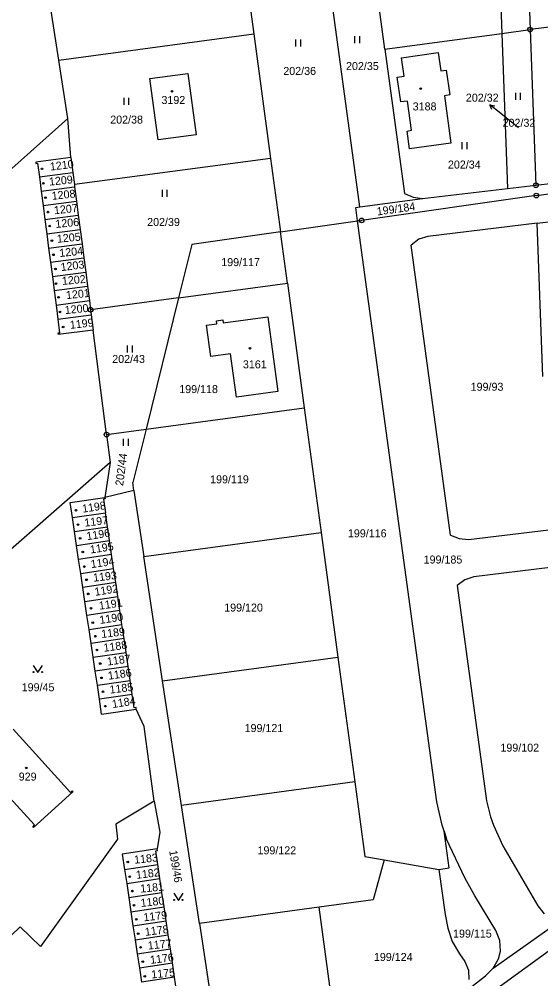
# Model space of a CAD drawing. Extents: x -735249 to -729401, y -1124843 to -1121828.
# Drawn here: x -732943.4 to -732832.6, y -1123775.2 to -1123571.3 of the extents above; entities that cross this region are included whole.
import ezdxf

# ---------------------------------------------------------------- set-up
doc = ezdxf.new("R2010")
doc.units = 0
for name, color, linetype in [('Vrstva 1', 7, 'Continuous'), ('Vrstva 16', 7, 'Continuous'), ('Vrstva 18', 7, 'Continuous'), ('Vrstva 19', 7, 'Continuous'), ('Vrstva 25', 7, 'Continuous')]:
    doc.layers.add(name, color=color, linetype=linetype)

msp = doc.modelspace()

# ---------------------------------------------------------------- linework, layer by layer
at = {"layer": 'Vrstva 1'}
for points in [[(-732842, -1123542.92), (-732840.85, -1123574.33)], [(-732836.01, -1123542.25), (-732834.87, -1123573.52)], [(-732871.03, -1123611.19), (-732879.7, -1123546.83)], [(-732865.69, -1123577.69), (-732869.97, -1123546.01)], [(-732897.13, -1123547.94), (-732893.56, -1123574.4)], [(-732934.95, -1123580.03), (-732936.92, -1123567.25)], [(-732817.38, -1123571.4), (-732834.87, -1123573.52)], [(-732840.85, -1123574.33), (-732834.87, -1123573.52)], [(-732834.87, -1123573.52), (-732833.63, -1123606.6)], [(-732934.95, -1123580.03), (-732893.56, -1123574.4)], [(-732893.56, -1123574.4), (-732889.98, -1123600.89)], [(-732865.69, -1123577.69), (-732840.85, -1123574.33)], [(-732840.85, -1123574.33), (-732839.65, -1123607.29)], [(-732865.69, -1123577.69), (-732861.55, -1123608.36)], [(-732862.15, -1123579.48), (-732854.39, -1123578.35)], [(-732861.61, -1123583.4), (-732862.15, -1123579.48)], [(-732854.39, -1123578.35), (-732853.79, -1123582.31)], [(-732933.04, -1123592.37), (-732934.95, -1123580.03)], [(-732915.61, -1123583.93), (-732907.52, -1123582.85)], [(-732907.52, -1123582.85), (-732905.79, -1123595.87)], [(-732863.07, -1123583.62), (-732861.61, -1123583.4)], [(-732862.32, -1123588.88), (-732863.07, -1123583.62)], [(-732853.79, -1123582.31), (-732852.65, -1123582.15)], [(-732852.65, -1123582.15), (-732851.87, -1123587.41)], [(-732913.86, -1123596.95), (-732915.61, -1123583.93)], [(-732851.87, -1123587.41), (-732853.07, -1123587.62)], [(-732853.07, -1123587.62), (-732851.7, -1123597.62)], [(-732860.86, -1123588.74), (-732862.32, -1123588.88)], [(-732860.02, -1123594.89), (-732860.86, -1123588.74)], [(-732933.04, -1123592.37), (-732988.63, -1123641.96)], [(-732932.39, -1123600.7), (-732933.04, -1123592.37)], [(-732905.79, -1123595.87), (-732913.86, -1123596.95)], [(-732860.98, -1123595.07), (-732860.02, -1123594.89)], [(-732860.49, -1123598.84), (-732860.98, -1123595.07)], [(-732851.7, -1123597.62), (-732860.49, -1123598.84)], [(-732932.39, -1123600.7), (-732939.85, -1123601.67)], [(-732939.85, -1123601.67), (-732939.82, -1123601.94)], [(-732939.82, -1123601.94), (-732939.45, -1123601.89)], [(-732939.45, -1123601.89), (-732939.07, -1123604.81)], [(-732932.39, -1123600.7), (-732931.98, -1123603.89)], [(-732889.98, -1123600.89), (-732931.64, -1123606.45)], [(-732889.98, -1123600.89), (-732887.87, -1123616.49)], [(-732939.07, -1123604.81), (-732931.98, -1123603.89)], [(-732931.98, -1123603.89), (-732931.64, -1123606.45)], [(-732939.07, -1123604.81), (-732938.68, -1123607.83)], [(-732938.68, -1123607.83), (-732931.58, -1123606.91)], [(-732938.68, -1123607.83), (-732938.28, -1123610.87)], [(-732931.64, -1123606.45), (-732931.58, -1123606.91)], [(-732931.58, -1123606.91), (-732931.19, -1123609.94)], [(-732857.69, -1123609.38), (-732839.65, -1123607.29)], [(-732839.65, -1123607.29), (-732833.63, -1123606.6)], [(-732833.63, -1123606.6), (-732830, -1123606.18)], [(-732938.28, -1123610.87), (-732931.19, -1123609.94)], [(-732931.19, -1123609.94), (-732930.8, -1123612.95)], [(-732871.03, -1123611.19), (-732857.69, -1123609.38)], [(-732833.55, -1123608.79), (-732870.64, -1123614.05)], [(-732861.55, -1123608.36), (-732859.69, -1123609.13)], [(-732859.69, -1123609.13), (-732857.69, -1123609.38)], [(-732833.55, -1123608.79), (-732830.81, -1123608.4)], [(-732938.28, -1123610.87), (-732937.89, -1123613.88)], [(-732871.87, -1123611.3), (-732871.03, -1123611.19)], [(-732871.48, -1123614.17), (-732871.87, -1123611.3)], [(-732833.34, -1123614.64), (-732801.13, -1123610.73)], [(-732937.89, -1123613.88), (-732930.8, -1123612.95)], [(-732937.89, -1123613.88), (-732937.5, -1123616.9)], [(-732930.8, -1123612.95), (-732930.41, -1123615.98)], [(-732887.87, -1123616.49), (-732871.48, -1123614.17)], [(-732871.48, -1123614.17), (-732870.64, -1123614.05)], [(-732854.63, -1123737.58), (-732871.48, -1123614.17)], [(-732937.5, -1123616.9), (-732930.41, -1123615.98)], [(-732930.41, -1123615.98), (-732930.01, -1123619.01)], [(-732833.34, -1123614.64), (-732856.61, -1123617.46)], [(-732832.12, -1123647.23), (-732833.34, -1123614.64)], [(-732937.5, -1123616.9), (-732937.1, -1123619.93)], [(-732887.87, -1123616.49), (-732906.73, -1123619.17)], [(-732886.4, -1123627.38), (-732887.87, -1123616.49)], [(-732858.51, -1123618.07), (-732860.1, -1123619.29)], [(-732856.61, -1123617.46), (-732858.51, -1123618.07)], [(-732937.1, -1123619.93), (-732930.01, -1123619.01)], [(-732937.1, -1123619.93), (-732936.71, -1123622.94)], [(-732930.01, -1123619.01), (-732929.62, -1123622.02)], [(-732906.73, -1123619.17), (-732909.53, -1123630.51)], [(-732851.77, -1123680.94), (-732860.1, -1123619.29)], [(-732936.71, -1123622.94), (-732929.62, -1123622.02)], [(-732929.62, -1123622.02), (-732929.23, -1123625.04)], [(-732936.71, -1123622.94), (-732936.32, -1123625.96)], [(-732936.32, -1123625.96), (-732929.23, -1123625.04)], [(-732936.32, -1123625.96), (-732935.93, -1123628.98)], [(-732929.23, -1123625.04), (-732928.84, -1123628.06)], [(-732935.93, -1123628.98), (-732928.84, -1123628.06)], [(-732928.84, -1123628.06), (-732928.44, -1123631.11)], [(-732909.53, -1123630.51), (-732886.4, -1123627.38)], [(-732886.4, -1123627.38), (-732882.82, -1123653.88)], [(-732935.93, -1123628.98), (-732935.53, -1123632.04)], [(-732909.53, -1123630.51), (-732928.19, -1123633.03)], [(-732909.53, -1123630.51), (-732916.42, -1123658.42)], [(-732935.53, -1123632.04), (-732928.44, -1123631.11)], [(-732935.53, -1123632.04), (-732935.14, -1123635.05)], [(-732928.44, -1123631.11), (-732928.19, -1123633.03)], [(-732935.14, -1123635.05), (-732928.05, -1123634.12)], [(-732928.19, -1123633.03), (-732928.05, -1123634.12)], [(-732928.05, -1123634.12), (-732927.63, -1123637.35)], [(-732900.01, -1123635.84), (-732890.56, -1123634.57)], [(-732890.56, -1123634.57), (-732888.44, -1123650.41)], [(-732935.14, -1123635.05), (-732934.78, -1123638)], [(-732903.56, -1123636.32), (-732901.38, -1123636.03)], [(-732902.65, -1123643), (-732903.56, -1123636.32)], [(-732901.46, -1123635.38), (-732900.09, -1123635.2)], [(-732901.38, -1123636.03), (-732901.46, -1123635.38)], [(-732900.09, -1123635.2), (-732900.01, -1123635.84)], [(-732934.78, -1123638), (-732935.13, -1123638.04)], [(-732935.13, -1123638.04), (-732935.09, -1123638.32)], [(-732927.63, -1123637.35), (-732935.09, -1123638.32)], [(-732924.81, -1123659.55), (-732927.63, -1123637.35)], [(-732898.45, -1123642.43), (-732902.65, -1123643)], [(-732897.21, -1123651.59), (-732898.45, -1123642.43)], [(-732888.44, -1123650.41), (-732897.21, -1123651.59)], [(-732916.42, -1123658.42), (-732882.82, -1123653.88)], [(-732882.82, -1123653.88), (-732879.24, -1123680.38)], [(-732924.81, -1123659.55), (-732916.42, -1123658.42)], [(-732916.42, -1123658.42), (-732919.22, -1123669.78)], [(-732924.81, -1123659.55), (-732924.06, -1123665.47)], [(-732924.06, -1123665.47), (-732971.48, -1123706.97)], [(-732924.06, -1123665.47), (-732925.16, -1123672.93)], [(-732919.02, -1123671.48), (-732919.22, -1123669.78)], [(-732932.52, -1123674.02), (-732925.16, -1123672.93)], [(-732925.11, -1123673.24), (-732925.49, -1123673.29)], [(-732925.49, -1123673.29), (-732925.06, -1123676.16)], [(-732919.02, -1123671.48), (-732925.16, -1123672.93)], [(-732925.16, -1123672.93), (-732925.11, -1123673.24)], [(-732919.02, -1123671.48), (-732916.9, -1123685.46)], [(-732932.05, -1123677.2), (-732932.52, -1123674.02)], [(-732932.05, -1123677.2), (-732925.06, -1123676.16)], [(-732931.61, -1123680.17), (-732932.05, -1123677.2)], [(-732924.62, -1123679.13), (-732925.06, -1123676.16)], [(-732931.61, -1123680.17), (-732924.62, -1123679.13)], [(-732924.18, -1123682.1), (-732924.62, -1123679.13)], [(-732931.17, -1123683.14), (-732931.61, -1123680.17)], [(-732916.9, -1123685.46), (-732879.24, -1123680.38)], [(-732879.24, -1123680.38), (-732875.66, -1123706.88)], [(-732851.77, -1123680.94), (-732849.9, -1123681.64)], [(-732847.91, -1123681.88), (-732830.9, -1123679.81)], [(-732931.17, -1123683.14), (-732924.18, -1123682.1)], [(-732930.73, -1123686.11), (-732931.17, -1123683.14)], [(-732923.74, -1123685.07), (-732924.18, -1123682.1)], [(-732849.9, -1123681.64), (-732847.91, -1123681.88)], [(-732923.74, -1123685.07), (-732930.73, -1123686.11)], [(-732923.3, -1123688.04), (-732923.74, -1123685.07)], [(-732912.9, -1123711.92), (-732916.9, -1123685.46)], [(-732930.29, -1123689.08), (-732930.73, -1123686.11)], [(-732930.29, -1123689.08), (-732923.3, -1123688.04)], [(-732929.85, -1123692.05), (-732930.29, -1123689.08)], [(-732922.86, -1123691.01), (-732923.3, -1123688.04)], [(-732830.6, -1123687.83), (-732846.84, -1123689.8)], [(-732922.86, -1123691.01), (-732929.85, -1123692.05)], [(-732922.42, -1123693.98), (-732922.86, -1123691.01)], [(-732848.74, -1123690.41), (-732850.33, -1123691.63)], [(-732850.33, -1123691.63), (-732844.15, -1123737.41)], [(-732846.84, -1123689.8), (-732848.74, -1123690.41)], [(-732929.4, -1123695.02), (-732929.85, -1123692.05)], [(-732929.4, -1123695.02), (-732922.42, -1123693.98)], [(-732928.96, -1123697.98), (-732929.4, -1123695.02)], [(-732921.98, -1123696.95), (-732922.42, -1123693.98)], [(-732921.98, -1123696.95), (-732928.96, -1123697.98)], [(-732921.54, -1123699.92), (-732921.98, -1123696.95)], [(-732928.52, -1123700.95), (-732928.96, -1123697.98)], [(-732928.52, -1123700.95), (-732921.54, -1123699.92)], [(-732921.1, -1123702.89), (-732921.54, -1123699.92)], [(-732928.08, -1123703.92), (-732928.52, -1123700.95)], [(-732921.1, -1123702.89), (-732928.08, -1123703.92)], [(-732927.64, -1123706.88), (-732928.08, -1123703.92)], [(-732920.66, -1123705.85), (-732921.1, -1123702.89)], [(-732927.64, -1123706.88), (-732920.66, -1123705.85)], [(-732920.22, -1123708.82), (-732920.66, -1123705.85)], [(-732927.2, -1123709.85), (-732927.64, -1123706.88)], [(-732912.9, -1123711.92), (-732875.66, -1123706.88)], [(-732875.66, -1123706.88), (-732872.08, -1123733.38)], [(-732920.22, -1123708.82), (-732927.2, -1123709.85)], [(-732926.76, -1123712.83), (-732927.2, -1123709.85)], [(-732919.78, -1123711.8), (-732920.22, -1123708.82)], [(-732926.76, -1123712.83), (-732919.78, -1123711.8)], [(-732919.34, -1123714.77), (-732919.78, -1123711.8)], [(-732908.89, -1123738.36), (-732912.9, -1123711.92)], [(-732926.32, -1123715.8), (-732926.76, -1123712.83)], [(-732919.34, -1123714.77), (-732926.32, -1123715.8)], [(-732925.85, -1123718.97), (-732926.32, -1123715.8)], [(-732918.91, -1123717.64), (-732919.34, -1123714.77)], [(-732925.85, -1123718.97), (-732918.49, -1123717.88)], [(-732918.53, -1123717.58), (-732918.91, -1123717.64)], [(-732918.49, -1123717.88), (-732918.53, -1123717.58)], [(-732916.79, -1123721.6), (-732918.49, -1123717.88)], [(-732944.65, -1123722.14), (-732932.47, -1123735.62)], [(-732914.68, -1123737.48), (-732916.79, -1123721.6)], [(-732872.08, -1123733.38), (-732908.89, -1123738.36)], [(-732872.08, -1123733.38), (-732869.94, -1123749.22)], [(-732940.09, -1123742.51), (-732946.1, -1123735.87)], [(-732931.94, -1123735.46), (-732940.34, -1123743.07)], [(-732932.47, -1123735.62), (-732932.1, -1123735.28)], [(-732932.1, -1123735.28), (-732931.94, -1123735.46)], [(-732914.68, -1123737.48), (-732922.85, -1123742.33)], [(-732914.68, -1123737.48), (-732913.5, -1123744.02)], [(-732905.1, -1123763.42), (-732908.89, -1123738.36)], [(-732853.51, -1123742.57), (-732854.63, -1123737.58)], [(-732844.15, -1123737.41), (-732843.27, -1123740.79)], [(-732940.48, -1123742.91), (-732940.09, -1123742.51)], [(-732922.85, -1123742.33), (-732922.45, -1123745.5)], [(-732853.11, -1123743.85), (-732853.51, -1123742.57)], [(-732843.27, -1123740.79), (-732842.64, -1123742.52)], [(-732842.64, -1123742.52), (-732840.65, -1123746.91)], [(-732940.34, -1123743.07), (-732940.48, -1123742.91)], [(-732913.5, -1123744.02), (-732914.07, -1123747.61)], [(-732852.06, -1123751.64), (-732853.11, -1123743.85)], [(-732853.11, -1123743.85), (-732852.58, -1123745.56)], [(-732922.45, -1123745.5), (-732938.82, -1123768.3)], [(-732848.72, -1123753.77), (-732852.58, -1123745.56)], [(-732914.07, -1123747.61), (-732921.46, -1123748.72)], [(-732921.46, -1123748.72), (-732920.97, -1123751.97)], [(-732914.36, -1123748.02), (-732914.02, -1123747.97)], [(-732913.93, -1123750.91), (-732914.36, -1123748.02)], [(-732914.02, -1123747.97), (-732914.07, -1123747.61)], [(-732840.65, -1123746.91), (-732833.21, -1123759.68)], [(-732920.97, -1123751.97), (-732913.93, -1123750.91)], [(-732913.48, -1123753.9), (-732913.93, -1123750.91)], [(-732869.94, -1123749.22), (-732865.82, -1123749.93)], [(-732865.82, -1123749.93), (-732868.16, -1123758.45)], [(-732865.82, -1123749.93), (-732854.22, -1123751.94)], [(-732920.97, -1123751.97), (-732920.53, -1123754.95)], [(-732854.22, -1123751.94), (-732852.06, -1123751.64)], [(-732854.22, -1123751.94), (-732852.92, -1123761.51)], [(-732920.53, -1123754.95), (-732913.48, -1123753.9)], [(-732920.53, -1123754.95), (-732920.08, -1123757.95)], [(-732913.04, -1123756.89), (-732913.48, -1123753.9)], [(-732846.56, -1123757.55), (-732848.72, -1123753.77)], [(-732920.08, -1123757.95), (-732913.04, -1123756.89)], [(-732912.59, -1123759.88), (-732913.04, -1123756.89)], [(-732920.08, -1123757.95), (-732919.63, -1123760.94)], [(-732868.16, -1123758.45), (-732879.67, -1123760)], [(-732842.11, -1123764.94), (-732846.56, -1123757.55)], [(-732919.63, -1123760.94), (-732912.59, -1123759.88)], [(-732919.63, -1123760.94), (-732919.19, -1123763.91)], [(-732912.14, -1123762.86), (-732912.59, -1123759.88)], [(-732879.67, -1123760), (-732905.1, -1123763.42)], [(-732875, -1123794.6), (-732879.67, -1123760)], [(-732833.21, -1123759.68), (-732831.87, -1123761.42)], [(-732919.19, -1123763.91), (-732912.14, -1123762.86)], [(-732911.7, -1123765.84), (-732912.14, -1123762.86)], [(-732866.57, -1123795.21), (-732820.7, -1123761.83)], [(-732852.92, -1123761.51), (-732852.36, -1123764.46)], [(-732842.69, -1123772.93), (-732828.89, -1123763.16)], [(-732943.14, -1123764.12), (-732958.19, -1123778.54)], [(-732938.82, -1123768.3), (-732943.14, -1123764.12)], [(-732919.19, -1123763.91), (-732918.74, -1123766.9)], [(-732905.1, -1123763.42), (-732899.12, -1123802.95)], [(-732852.36, -1123764.46), (-732851.39, -1123767.3)], [(-732841.25, -1123767.09), (-732842.11, -1123764.94)], [(-732918.74, -1123766.9), (-732911.7, -1123765.84)], [(-732918.74, -1123766.9), (-732918.29, -1123769.89)], [(-732911.25, -1123768.83), (-732911.7, -1123765.84)], [(-732841.17, -1123769.29), (-732841.25, -1123767.09)], [(-732918.29, -1123769.89), (-732911.25, -1123768.83)], [(-732910.8, -1123771.83), (-732911.25, -1123768.83)], [(-732851.39, -1123767.3), (-732849.85, -1123769.87)], [(-732918.29, -1123769.89), (-732917.84, -1123772.89)], [(-732849.85, -1123769.87), (-732848.71, -1123771.51)], [(-732842.69, -1123772.93), (-732841.59, -1123770.97)], [(-732841.59, -1123770.97), (-732841.17, -1123769.29)], [(-732917.84, -1123772.89), (-732910.8, -1123771.83)], [(-732917.84, -1123772.89), (-732917.4, -1123775.88)], [(-732910.35, -1123774.82), (-732910.8, -1123771.83)], [(-732848.71, -1123771.51), (-732847.97, -1123773.37)], [(-732844.32, -1123774.55), (-732842.69, -1123772.93)], [(-732910.35, -1123774.82), (-732917.4, -1123775.88)], [(-732909.92, -1123777.71), (-732910.35, -1123774.82)], [(-732849.78, -1123778.85), (-732844.32, -1123774.55)], [(-732847.97, -1123773.37), (-732847.88, -1123775.37)]]:
    msp.add_lwpolyline(points, dxfattribs=at)
at = {"layer": 'Vrstva 16'}
msp.add_lwpolyline([(-732837.3, -1123594.36), (-732841.09, -1123591.36)], dxfattribs=at)
at = {"layer": 'Vrstva 25'}
for points in [[(-732872.067, -1123576.395), (-732872.067, -1123574.895)], [(-732871.033, -1123576.395), (-732871.033, -1123574.895)], [(-732884.577, -1123577.095), (-732884.577, -1123575.595)], [(-732883.543, -1123577.095), (-732883.543, -1123575.595)], [(-732837.897, -1123588.455), (-732837.897, -1123586.955)], [(-732836.863, -1123588.455), (-732836.863, -1123586.955)], [(-732921.087, -1123589.505), (-732921.087, -1123588.005)], [(-732920.053, -1123589.505), (-732920.053, -1123588.005)], [(-732841.09, -1123591.36), (-732843.437, -1123589.493)], [(-732842.966, -1123590.507), (-732843.437, -1123589.493), (-732842.343, -1123589.724)], [(-732849.257, -1123598.915), (-732849.257, -1123597.415)], [(-732848.223, -1123598.915), (-732848.223, -1123597.415)], [(-732912.957, -1123609.075), (-732912.957, -1123607.575)], [(-732911.923, -1123609.075), (-732911.923, -1123607.575)], [(-732920.347, -1123642.115), (-732920.347, -1123640.615)], [(-732919.313, -1123642.115), (-732919.313, -1123640.615)], [(-732921.197, -1123661.945), (-732921.197, -1123660.445)], [(-732920.163, -1123661.945), (-732920.163, -1123660.445)], [(-732940.41, -1123708.61), (-732939.41, -1123710.11), (-732938.41, -1123708.61)], [(-732910.55, -1123757.03), (-732909.55, -1123758.53), (-732908.55, -1123757.03)]]:
    msp.add_lwpolyline(points, dxfattribs=at)
for centre, radius in [((-732834.87, -1123573.52), 0.5), ((-732834.87, -1123573.52), 0.032), ((-732910.91, -1123586.63), 0.175), ((-732858.09, -1123586.05), 0.175), ((-732938.51, -1123603.1), 0.175), ((-732938.24, -1123606.19), 0.175), ((-732833.63, -1123606.6), 0.5), ((-732833.63, -1123606.6), 0.032), ((-732937.78, -1123609.22), 0.175), ((-732833.55, -1123608.79), 0.5), ((-732833.55, -1123608.79), 0.032), ((-732937.24, -1123612.29), 0.175), ((-732870.64, -1123614.05), 0.5), ((-732870.64, -1123614.05), 0.032), ((-732936.88, -1123615.26), 0.175), ((-732936.42, -1123618.35), 0.175), ((-732936.09, -1123621.37), 0.175), ((-732935.66, -1123624.38), 0.175), ((-732935.54, -1123627.47), 0.175), ((-732935, -1123630.41), 0.175), ((-732928.19, -1123633.03), 0.5), ((-732934.69, -1123633.51), 0.175), ((-732928.19, -1123633.03), 0.032), ((-732934.03, -1123636.72), 0.175), ((-732894.33, -1123641.21), 0.175), ((-732924.81, -1123659.55), 0.5), ((-732924.81, -1123659.55), 0.032), ((-732931.29, -1123675.64), 0.175), ((-732930.88, -1123678.69), 0.175), ((-732930.41, -1123681.6), 0.175), ((-732929.85, -1123684.5), 0.175), ((-732929.52, -1123687.61), 0.175), ((-732929.06, -1123690.42), 0.175), ((-732928.71, -1123693.41), 0.175), ((-732928.11, -1123696.46), 0.175), ((-732927.73, -1123699.53), 0.175), ((-732927.2, -1123702.4), 0.175), ((-732926.85, -1123705.33), 0.175), ((-732926.16, -1123708.22), 0.175), ((-732940.31, -1123710.01), 0.1), ((-732938.51, -1123710.01), 0.1), ((-732925.88, -1123711.25), 0.175), ((-732925.56, -1123714.21), 0.175), ((-732925.05, -1123717.27), 0.175), ((-732941.85, -1123730.39), 0.175), ((-732920.3, -1123750.37), 0.175), ((-732919.88, -1123753.51), 0.175), ((-732919.33, -1123756.56), 0.175), ((-732910.45, -1123758.43), 0.1), ((-732908.65, -1123758.43), 0.1), ((-732918.96, -1123759.56), 0.175), ((-732918.49, -1123762.56), 0.175), ((-732918.08, -1123765.61), 0.175), ((-732917.57, -1123768.52), 0.175), ((-732917.11, -1123771.57), 0.175), ((-732916.69, -1123774.66), 0.175)]:
    msp.add_circle(centre, radius, dxfattribs=at)

# ---------------------------------------------------------------- texts
at = {"layer": 'Vrstva 16'}
msp.add_text('202/32', height=1.7, dxfattribs=at).set_placement((-732848.498, -1123588.83))
at = {"layer": 'Vrstva 18'}
for s, p in [('202/36', (-732887.268, -1123583.15)), ('202/35', (-732873.948, -1123582.11)), ('202/38', (-732924.028, -1123593.49)), ('202/32', (-732840.698, -1123594.16)), ('202/34', (-732852.308, -1123603.04)), ('202/39', (-732916.188, -1123615.25)), ('199/117', (-732900.45, -1123623.77)), ('202/43', (-732923.6, -1123644.35)), ('199/118', (-732909.37, -1123650.75)), ('199/93', (-732847.48, -1123650.25)), ('199/119', (-732902.81, -1123669.92)), ('199/116', (-732873.55, -1123681.4)), ('199/185', (-732857.468, -1123686.96)), ('199/120', (-732899.82, -1123697.17)), ('199/45', (-732942.83, -1123714.1)), ('199/121', (-732895.49, -1123722.77)), ('199/102', (-732841.16, -1123726.93)), ('199/122', (-732892.75, -1123748.75)), ('199/115', (-732851.22, -1123766.44)), ('199/124', (-732868.03, -1123771.41))]:
    msp.add_text(s, height=1.7, dxfattribs=at).set_placement(p)
for s, rotation, p in [('199/184', 8.00006, (-732867.296, -1123613.022)), ('202/44', 82.60066, (-732921.302, -1123670.546)), ('199/46', 279.40222, (-732911.511, -1123748.004))]:
    msp.add_text(s, height=1.7, rotation=rotation, dxfattribs=at).set_placement(p)
at = {"layer": 'Vrstva 19'}
for s, p in [('3192', (-732913.153, -1123589.33)), ('3188', (-732859.793, -1123590.69)), ('3161', (-732895.85, -1123645.49)), ('929', (-732943.46, -1123733.08))]:
    msp.add_text(s, height=1.7, dxfattribs=at).set_placement(p)
for s, rotation, p in [('1210', 6.70005, (-732936.735, -1123603.479)), ('1209', 5.70004, (-732936.941, -1123606.672)), ('1208', 6.00005, (-732936.363, -1123609.701)), ('1207', 6.00005, (-732935.883, -1123612.761)), ('1206', 5.30004, (-732935.6, -1123615.673)), ('1205', 5.50004, (-732935.271, -1123618.822)), ('1204', 6.00005, (-732934.753, -1123621.851)), ('1203', 6.90006, (-732934.456, -1123624.838)), ('1202', 5.10004, (-732934.209, -1123627.774)), ('1201', 5.80005, (-732933.332, -1123630.801)), ('1200', 5.50004, (-732933.601, -1123633.972)), ('1199', 6.10005, (-732932.513, -1123637.11)), ('1198', 8.70007, (-732929.853, -1123676.173)), ('1197', 6.60005, (-732929.425, -1123679.139)), ('1196', 9.00007, (-732928.934, -1123682.012)), ('1195', 8.30007, (-732928.211, -1123684.844)), ('1194', 8.20006, (-732928.051, -1123687.954)), ('1193', 6.60005, (-732927.565, -1123690.839)), ('1192', 9.10007, (-732927.215, -1123693.841)), ('1191', 8.10006, (-732926.311, -1123696.784)), ('1190', 8.50007, (-732926.182, -1123699.803)), ('1189', 6.40005, (-732925.844, -1123702.779)), ('1188', 7.70006, (-732925.339, -1123705.726)), ('1187', 8.10006, (-732924.591, -1123708.664)), ('1186', 8.30007, (-732924.381, -1123711.664)), ('1185', 6.90006, (-732924.066, -1123714.608)), ('1184', 9.10007, (-732923.515, -1123717.681)), ('1183', 5.80005, (-732918.872, -1123750.751)), ('1182', 6.80005, (-732918.456, -1123753.978)), ('1181', 5.30004, (-732917.58, -1123756.893)), ('1180', 6.30005, (-732917.484, -1123759.94)), ('1179', 6.30005, (-732916.884, -1123762.99)), ('1178', 6.90006, (-732916.566, -1123766.078)), ('1177', 5.70004, (-732915.961, -1123768.992)), ('1176', 7.10006, (-732915.457, -1123772.037)), ('1175', 5.70004, (-732915.221, -1123775.132))]:
    msp.add_text(s, height=1.7, rotation=rotation, dxfattribs=at).set_placement(p)

doc.saveas('drawing.dxf')
